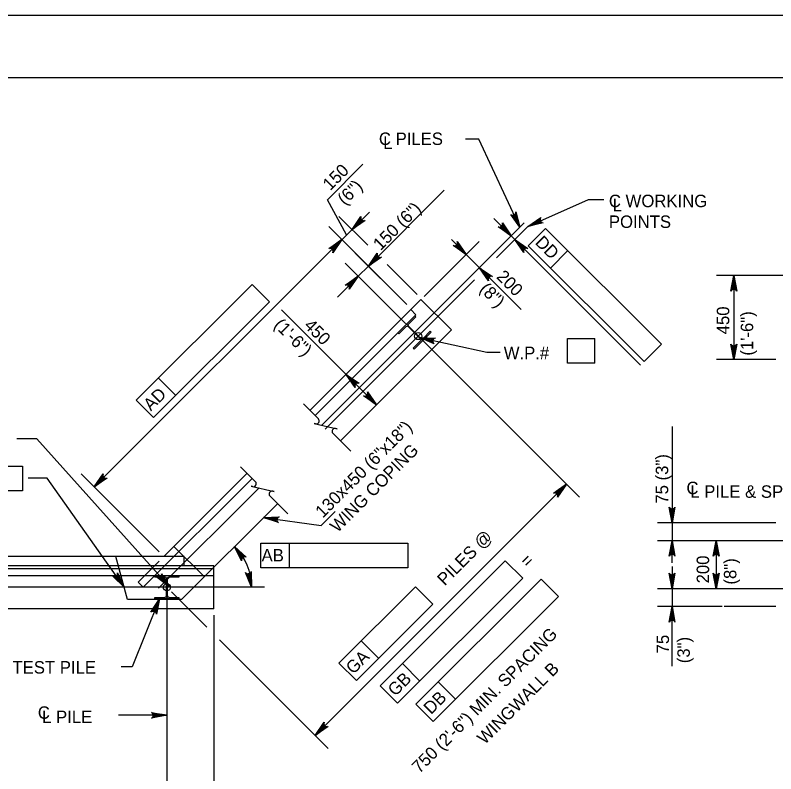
# Model space of a CAD drawing. Extents: x 635440 to 640306, y 296653 to 298484.
# Drawn here: x 639694 to 639876.7, y 298253.1 to 298435.5 of the extents above; entities that cross this region are included whole.
import ezdxf

# ---------------------------------------------------------------- set-up
doc = ezdxf.new("R2010")
doc.units = 0
for name, color, linetype in [('2', 7, 'Continuous'), ('3', 7, 'Continuous'), ('4', 7, 'Continuous'), ('5', 7, 'Continuous'), ('8', 7, 'Continuous'), ('PLT-BNDY', 7, 'Continuous')]:
    doc.layers.add(name, color=color, linetype=linetype)

# ---------------------------------------------------------------- blocks, each defined once
blk = doc.blocks.new('HPILE')
at = {"layer": '3'}
for p, q in [((-0.12, -2.66), (-0.12, 2.66)), ((0.12, 2.66), (0.12, -2.66)), ((-3.67, -3.1), (-0.56, -3.1))]:
    blk.add_line(p, q, dxfattribs=at)
for points in [[(-0.56, 3.1), (-3.67, 3.1), (-3.67, 3.54), (3.67, 3.54), (3.67, 3.1), (0.56, 3.1)], [(0.56, -3.1), (3.67, -3.1), (3.67, -3.54), (-3.67, -3.54), (-3.67, -3.1)]]:
    blk.add_lwpolyline(points, dxfattribs=at)
for centre, start, end in [((-0.56, 2.66), 0, 90), ((0.56, 2.66), 90, 180), ((-0.56, -2.66), 270, 0), ((0.56, -2.66), 180, 270)]:
    blk.add_arc(centre, 0.438, start, end, dxfattribs=at)

msp = doc.modelspace()

# ---------------------------------------------------------------- linework, layer by layer
at = {"layer": '2'}
for p, q in [((639316.46, 298420.46), (640102.46, 298420.46)), ((639764.81, 298340.42), (639791.48, 298367.09)), ((639791.48, 298367.09), (639798.79, 298359.78)), ((639772.11, 298333.11), (639798.79, 298359.78)), ((639729.7, 298305.31), (639749.69, 298325.31)), ((639733.98, 298294.98), (639757, 298318)), ((639732.13, 298307.75), (639739.44, 298300.44)), ((639729.7, 298305.31), (639483.12, 298305.31)), ((639720.95, 298294.98), (639718.19, 298305.31)), ((639741.68, 298292.76), (639741.68, 298302.68)), ((639724.75, 298297.93), (639723.53, 298299.15)), ((639733.98, 298294.98), (639720.95, 298294.98)), ((639741.68, 298292.76), (639472.28, 298292.76))]:
    msp.add_line(p, q, dxfattribs=at)
at = {"layer": '3'}
for p, q in [((639789.04, 298364.66), (639790.26, 298363.44)), ((639766.02, 298339.2), (639790.26, 298363.44)), ((639724.75, 298297.93), (639750.91, 298324.09)), ((639728.55, 298304.16), (639723.53, 298299.15)), ((639734.58, 298305.31), (639729.7, 298305.31)), ((639734.58, 298303.1), (639734.58, 298305.31)), ((639741.68, 298303.1), (639472.28, 298303.1)), ((639472.28, 298302.44), (639741.68, 298302.44)), ((639741.68, 298302.68), (639741.68, 298303.1)), ((639472.28, 298300.71), (639741.68, 298300.71))]:
    msp.add_line(p, q, dxfattribs=at)
at = {"layer": '4'}
for p, q in [((639805.4, 298405.65), (639802.18, 298405.65)), ((639769.02, 298391.1), (639777.53, 298399.6)), ((639778.83, 298375.14), (639797.07, 298393.38)), ((639773.59, 298382.61), (639769.02, 298391.1)), ((639831.75, 298391.11), (639835.37, 298391.11)), ((639778.69, 298380.15), (639771.78, 298387.06)), ((639774.91, 298383.93), (639779.09, 298388.11)), ((639813.16, 298382.4), (639808.99, 298386.58)), ((639788.09, 298365.88), (639769.34, 298384.63)), ((639795.6, 298364.84), (639816.3, 298385.53)), ((639809.59, 298377.09), (639817.16, 298384.67)), ((639770.04, 298379.06), (639774.91, 298383.93)), ((639821.42, 298384.19), (639817.25, 298380.02)), ((639821.42, 298384.19), (639849.27, 298356.35)), ((639712.99, 298322.02), (639772.47, 298381.49)), ((639792.24, 298367.86), (639805.46, 298381.07)), ((639802.32, 298377.94), (639798.78, 298381.49)), ((639813.16, 298382.4), (639814.03, 298381.53)), ((639814.03, 298381.53), (639844.24, 298351.33)), ((639770.39, 298379.41), (639768.3, 298377.32)), ((639817.25, 298380.02), (639845.09, 298352.18)), ((639788.09, 298365.88), (639775.7, 298378.27)), ((639805.51, 298374.75), (639802.33, 298377.94)), ((639826.77, 298378.85), (639822.6, 298374.67)), ((639773.26, 298375.83), (639802.31, 298346.79)), ((639790.53, 298368.32), (639783.33, 298375.51)), ((639778.83, 298375.14), (639776.39, 298372.7)), ((639805.51, 298374.75), (639815.55, 298364.71)), ((639776.39, 298372.7), (639771.39, 298367.7)), ((639796.47, 298363.97), (639804.35, 298371.85)), ((639881.05, 298372.84), (639862.47, 298372.84)), ((639866.62, 298372.84), (639866.62, 298352.66)), ((639723.05, 298342.87), (639750.89, 298370.71)), ((639750.89, 298370.71), (639755.07, 298366.53)), ((639727.23, 298338.69), (639755.07, 298366.53)), ((639773.49, 298349.1), (639757.98, 298364.61)), ((639767.63, 298336.87), (639796.16, 298365.4)), ((639768.43, 298335.93), (639796.96, 298364.47)), ((639826.69, 298351.82), (639826.69, 298357.72)), ((639826.69, 298357.72), (639833.28, 298357.72)), ((639833.28, 298351.82), (639833.28, 298357.72)), ((639849.27, 298356.35), (639845.09, 298352.18)), ((639774.09, 298349.7), (639776.62, 298352.24)), ((639833.28, 298351.82), (639826.69, 298351.82)), ((639876.69, 298352.66), (639862.47, 298352.66)), ((639728.4, 298348.21), (639732.58, 298344.04)), ((639780.8, 298341.8), (639773.49, 298349.1)), ((639802.31, 298346.79), (639829.55, 298319.54)), ((639781.4, 298342.39), (639783.93, 298344.93)), ((639723.05, 298342.87), (639727.23, 298338.69)), ((639851.8, 298336.58), (639851.8, 298313.44)), ((639654.53, 298327.02), (639695.74, 298327.02)), ((639695.74, 298327.02), (639695.74, 298321.11)), ((639728.61, 298306.4), (639709.86, 298325.15)), ((639766.05, 298262.3), (639826.42, 298322.67)), ((639695.74, 298321.11), (639654.53, 298321.11)), ((639728.45, 298297.69), (639752.52, 298321.76)), ((639728.61, 298306.4), (639716.22, 298318.79)), ((639876.69, 298313.44), (639848.28, 298313.44)), ((639851.8, 298313.44), (639851.8, 298309.11)), ((639753.01, 298308.53), (639788.31, 298308.53)), ((639753.01, 298302.62), (639753.01, 298308.53)), ((639759.85, 298302.62), (639759.85, 298308.53)), ((639788.31, 298308.53), (639788.31, 298302.62)), ((639904.09, 298309.11), (639848.28, 298309.11)), ((639851.8, 298303.75), (639851.8, 298309.11)), ((639862.39, 298309.11), (639862.39, 298297.57)), ((639781.67, 298274.2), (639811.74, 298304.27)), ((639811.74, 298304.27), (639815.91, 298300.09)), ((639788.31, 298302.62), (639753.01, 298302.62)), ((639851.8, 298302.92), (639851.8, 298297.57)), ((639785.85, 298270.02), (639815.91, 298300.09)), ((639790.24, 298269.81), (639820.31, 298299.88)), ((639820.31, 298299.88), (639824.49, 298295.7)), ((639753.9, 298297.93), (639458.72, 298297.93)), ((639731.51, 298296.84), (639740.04, 298288.32)), ((639771.78, 298279.69), (639790.12, 298298.03)), ((639790.12, 298298.03), (639794.3, 298293.85)), ((639893.99, 298297.57), (639848.28, 298297.57)), ((639851.8, 298297.57), (639851.8, 298293.25)), ((639730.43, 298296.39), (639730.43, 298236.13)), ((639794.42, 298265.63), (639824.49, 298295.7)), ((639775.96, 298275.51), (639794.3, 298293.85)), ((639863.83, 298293.25), (639848.28, 298293.25)), ((639851.8, 298278.96), (639851.8, 298293.25)), ((639876.69, 298293.25), (639864.34, 298293.25)), ((639741.68, 298291.22), (639741.68, 298221.99)), ((639743.11, 298285.24), (639769.19, 298259.17)), ((639777.13, 298285.03), (639781.3, 298280.86)), ((639722.12, 298278.77), (639719.42, 298278.77)), ((639771.78, 298279.69), (639775.96, 298275.51)), ((639787.02, 298279.55), (639791.19, 298275.37)), ((639795.59, 298275.16), (639799.77, 298270.98)), ((639781.67, 298274.2), (639785.85, 298270.02)), ((639790.24, 298269.81), (639794.42, 298265.63)), ((639730.43, 298267.13), (639718.81, 298267.13))]:
    msp.add_line(p, q, dxfattribs=at)
for points in [[(639815.24, 298384.48), (639805.4, 298405.65)], [(639817.16, 298384.67), (639831.75, 298391.11)], [(639815.24, 298384.48), (639813.04, 298387.57), (639813.34, 298387.39), (639813.63, 298387.36), (639813.87, 298387.43), (639814.08, 298387.57), (639814.24, 298387.81), (639814.3, 298388.16), (639815.24, 298384.48), (639814.24, 298387.81), (639814.08, 298387.57), (639815.24, 298384.48), (639813.87, 298387.43), (639813.63, 298387.36), (639815.24, 298384.48), (639813.34, 298387.39)], [(639774.91, 298383.93), (639777.05, 298387.06), (639776.99, 298386.72), (639777.06, 298386.43), (639777.21, 298386.23), (639777.41, 298386.08), (639777.7, 298386.01), (639778.04, 298386.07), (639774.91, 298383.93), (639777.7, 298386.01), (639777.41, 298386.08), (639774.91, 298383.93), (639777.21, 298386.23), (639777.06, 298386.43), (639774.91, 298383.93), (639776.99, 298386.72)], [(639817.16, 298384.67), (639820.29, 298386.81), (639820.11, 298386.51), (639820.07, 298386.23), (639820.14, 298385.98), (639820.28, 298385.77), (639820.51, 298385.6), (639820.86, 298385.53), (639817.16, 298384.67), (639820.51, 298385.6), (639820.28, 298385.77), (639817.16, 298384.67), (639820.14, 298385.98), (639820.07, 298386.23), (639817.16, 298384.67), (639820.11, 298386.51)], [(639813.16, 298382.4), (639810.03, 298384.55), (639810.38, 298384.48), (639810.66, 298384.56), (639810.87, 298384.7), (639811.01, 298384.91), (639811.08, 298385.19), (639811.02, 298385.53), (639813.16, 298382.4), (639811.08, 298385.19), (639811.01, 298384.91), (639813.16, 298382.4), (639810.87, 298384.7), (639810.66, 298384.56), (639813.16, 298382.4), (639810.38, 298384.48)], [(639772.47, 298381.49), (639770.33, 298378.36), (639770.39, 298378.71), (639770.32, 298378.99), (639770.17, 298379.2), (639769.97, 298379.34), (639769.69, 298379.42), (639769.34, 298379.35), (639772.47, 298381.49), (639769.69, 298379.42), (639769.97, 298379.34), (639772.47, 298381.49), (639770.17, 298379.2), (639770.32, 298378.99), (639772.47, 298381.49), (639770.39, 298378.71)], [(639802.32, 298377.94), (639799.19, 298380.08), (639799.54, 298380.02), (639799.82, 298380.09), (639800.03, 298380.24), (639800.17, 298380.44), (639800.24, 298380.73), (639800.18, 298381.07), (639802.32, 298377.94), (639800.24, 298380.73), (639800.17, 298380.44), (639802.32, 298377.94), (639800.03, 298380.24), (639799.82, 298380.09), (639802.32, 298377.94), (639799.54, 298380.02)], [(639814.03, 298381.53), (639817.16, 298379.39), (639816.82, 298379.46), (639816.54, 298379.38), (639816.33, 298379.24), (639816.19, 298379.03), (639816.11, 298378.75), (639816.17, 298378.4), (639814.03, 298381.53), (639816.11, 298378.75), (639816.19, 298379.03), (639814.03, 298381.53), (639816.33, 298379.24), (639816.54, 298379.38), (639814.03, 298381.53), (639816.82, 298379.46)], [(639778.83, 298375.14), (639780.97, 298378.27), (639780.91, 298377.93), (639780.98, 298377.64), (639781.13, 298377.44), (639781.34, 298377.29), (639781.62, 298377.22), (639781.96, 298377.28), (639778.83, 298375.14), (639781.62, 298377.22), (639781.34, 298377.29), (639778.83, 298375.14), (639781.13, 298377.44), (639780.98, 298377.64), (639778.83, 298375.14), (639780.91, 298377.93)], [(639805.51, 298374.75), (639808.65, 298372.61), (639808.3, 298372.67), (639808.02, 298372.6), (639807.81, 298372.45), (639807.67, 298372.25), (639807.59, 298371.97), (639807.66, 298371.62), (639805.51, 298374.75), (639807.59, 298371.97), (639807.67, 298372.25), (639805.51, 298374.75), (639807.81, 298372.45), (639808.02, 298372.6), (639805.51, 298374.75), (639808.3, 298372.67)], [(639776.39, 298372.7), (639774.25, 298369.57), (639774.31, 298369.91), (639774.24, 298370.2), (639774.1, 298370.4), (639773.89, 298370.55), (639773.61, 298370.62), (639773.26, 298370.56), (639776.39, 298372.7), (639773.61, 298370.62), (639773.89, 298370.55), (639776.39, 298372.7), (639774.1, 298370.4), (639774.24, 298370.2), (639776.39, 298372.7), (639774.31, 298369.91)], [(639866.62, 298372.84), (639867.32, 298369.12), (639867.12, 298369.4), (639866.87, 298369.55), (639866.62, 298369.59), (639866.37, 298369.55), (639866.12, 298369.4), (639865.92, 298369.12), (639866.62, 298372.84), (639866.12, 298369.4), (639866.37, 298369.55), (639866.62, 298372.84), (639866.62, 298369.59), (639866.87, 298369.55), (639866.62, 298372.84), (639867.12, 298369.4)], [(639791.15, 298357.95), (639807.27, 298354.4), (639810.49, 298354.4)], [(639791.15, 298357.95), (639794.94, 298357.83), (639794.62, 298357.69), (639794.42, 298357.48), (639794.32, 298357.25), (639794.31, 298356.99), (639794.4, 298356.72), (639794.64, 298356.46), (639791.15, 298357.95), (639794.4, 298356.72), (639794.31, 298356.99), (639791.15, 298357.95), (639794.32, 298357.25), (639794.42, 298357.48), (639791.15, 298357.95), (639794.62, 298357.69)], [(639866.62, 298352.66), (639865.92, 298356.39), (639866.12, 298356.1), (639866.37, 298355.95), (639866.62, 298355.91), (639866.87, 298355.95), (639867.12, 298356.1), (639867.32, 298356.39), (639866.62, 298352.66), (639867.12, 298356.1), (639866.87, 298355.95), (639866.62, 298352.66), (639866.62, 298355.91), (639866.37, 298355.95), (639866.62, 298352.66), (639866.12, 298356.1)], [(639773.49, 298349.1), (639776.62, 298346.96), (639776.27, 298347.02), (639775.99, 298346.95), (639775.79, 298346.81), (639775.64, 298346.6), (639775.57, 298346.32), (639775.63, 298345.97), (639773.49, 298349.1), (639775.57, 298346.32), (639775.64, 298346.6), (639773.49, 298349.1), (639775.79, 298346.81), (639775.99, 298346.95), (639773.49, 298349.1), (639776.27, 298347.02)], [(639780.8, 298341.8), (639777.66, 298343.94), (639778.01, 298343.87), (639778.29, 298343.95), (639778.5, 298344.09), (639778.64, 298344.3), (639778.72, 298344.58), (639778.65, 298344.93), (639780.8, 298341.8), (639778.72, 298344.58), (639778.64, 298344.3), (639780.8, 298341.8), (639778.5, 298344.09), (639778.29, 298343.95), (639780.8, 298341.8), (639778.01, 298343.87)], [(639731.13, 298297.93), (639699.16, 298333.61), (639694.39, 298333.61)], [(639712.99, 298322.02), (639715.13, 298325.15), (639715.07, 298324.8), (639715.15, 298324.52), (639715.29, 298324.31), (639715.5, 298324.17), (639715.78, 298324.09), (639716.12, 298324.16), (639712.99, 298322.02), (639715.78, 298324.09), (639715.5, 298324.17), (639712.99, 298322.02), (639715.29, 298324.31), (639715.15, 298324.52), (639712.99, 298322.02), (639715.07, 298324.8)], [(639720.16, 298297.93), (639701.71, 298324.18), (639697.1, 298324.18)], [(639826.42, 298322.67), (639824.28, 298319.54), (639824.34, 298319.89), (639824.27, 298320.17), (639824.12, 298320.38), (639823.92, 298320.52), (639823.63, 298320.59), (639823.29, 298320.53), (639826.42, 298322.67), (639823.63, 298320.59), (639823.92, 298320.52), (639826.42, 298322.67), (639824.12, 298320.38), (639824.27, 298320.17), (639826.42, 298322.67), (639824.34, 298319.89)], [(639851.8, 298313.44), (639851.1, 298317.17), (639851.3, 298316.88), (639851.55, 298316.73), (639851.8, 298316.69), (639852.05, 298316.73), (639852.3, 298316.88), (639852.5, 298317.17), (639851.8, 298313.44), (639852.3, 298316.88), (639852.05, 298316.73), (639851.8, 298313.44), (639851.8, 298316.69), (639851.55, 298316.73), (639851.8, 298313.44), (639851.3, 298316.88)], [(639753.65, 298314.65), (639767.53, 298312.73), (639770.89, 298316.09)], [(639753.65, 298314.65), (639757.44, 298314.83), (639757.12, 298314.68), (639756.94, 298314.45), (639756.87, 298314.2), (639756.88, 298313.95), (639756.99, 298313.68), (639757.24, 298313.45), (639753.65, 298314.65), (639756.99, 298313.68), (639756.88, 298313.95), (639753.65, 298314.65), (639756.87, 298314.2), (639756.94, 298314.45), (639753.65, 298314.65), (639757.12, 298314.68)], [(639851.8, 298309.11), (639852.5, 298305.38), (639852.3, 298305.67), (639852.05, 298305.82), (639851.8, 298305.86), (639851.55, 298305.82), (639851.3, 298305.67), (639851.1, 298305.38), (639851.8, 298309.11), (639851.3, 298305.67), (639851.55, 298305.82), (639851.8, 298309.11), (639851.8, 298305.86), (639852.05, 298305.82), (639851.8, 298309.11), (639852.3, 298305.67)], [(639862.39, 298309.11), (639863.09, 298305.38), (639862.89, 298305.67), (639862.64, 298305.82), (639862.39, 298305.86), (639862.14, 298305.82), (639861.89, 298305.67), (639861.69, 298305.38), (639862.39, 298309.11), (639861.89, 298305.67), (639862.14, 298305.82), (639862.39, 298309.11), (639862.39, 298305.86), (639862.64, 298305.82), (639862.39, 298309.11), (639862.89, 298305.67)], [(639746.71, 298307.71), (639749.5, 298305.14), (639749.17, 298305.25), (639748.88, 298305.22), (639748.66, 298305.1), (639748.48, 298304.92), (639748.37, 298304.65), (639748.38, 298304.3), (639746.71, 298307.71), (639748.37, 298304.65), (639748.48, 298304.92), (639746.71, 298307.71), (639748.66, 298305.1), (639748.88, 298305.22), (639746.71, 298307.71), (639749.17, 298305.25)], [(639720.16, 298297.93), (639717.44, 298300.58), (639717.77, 298300.46), (639718.06, 298300.48), (639718.29, 298300.59), (639718.47, 298300.77), (639718.59, 298301.03), (639718.59, 298301.38), (639720.16, 298297.93), (639718.59, 298301.03), (639718.47, 298300.77), (639720.16, 298297.93), (639718.29, 298300.59), (639718.06, 298300.48), (639720.16, 298297.93), (639717.77, 298300.46)], [(639731.13, 298297.93), (639728.12, 298300.24), (639728.46, 298300.16), (639728.75, 298300.21), (639728.96, 298300.35), (639729.12, 298300.55), (639729.21, 298300.82), (639729.16, 298301.17), (639731.13, 298297.93), (639729.21, 298300.82), (639729.12, 298300.55), (639731.13, 298297.93), (639728.96, 298300.35), (639728.75, 298300.21), (639731.13, 298297.93), (639728.46, 298300.16)], [(639750.76, 298297.93), (639749.34, 298301.45), (639749.59, 298301.21), (639749.87, 298301.11), (639750.12, 298301.12), (639750.36, 298301.21), (639750.58, 298301.4), (639750.72, 298301.72), (639750.76, 298297.93), (639750.58, 298301.4), (639750.36, 298301.21), (639750.76, 298297.93), (639750.12, 298301.12), (639749.87, 298301.11), (639750.76, 298297.93), (639749.59, 298301.21)], [(639851.8, 298297.57), (639851.1, 298301.3), (639851.3, 298301.02), (639851.55, 298300.87), (639851.8, 298300.82), (639852.05, 298300.87), (639852.3, 298301.02), (639852.5, 298301.3), (639851.8, 298297.57), (639852.3, 298301.02), (639852.05, 298300.87), (639851.8, 298297.57), (639851.8, 298300.82), (639851.55, 298300.87), (639851.8, 298297.57), (639851.3, 298301.02)], [(639862.39, 298297.57), (639861.69, 298301.3), (639861.89, 298301.02), (639862.14, 298300.87), (639862.39, 298300.82), (639862.64, 298300.87), (639862.89, 298301.02), (639863.09, 298301.3), (639862.39, 298297.57), (639862.89, 298301.02), (639862.64, 298300.87), (639862.39, 298297.57), (639862.39, 298300.82), (639862.14, 298300.87), (639862.39, 298297.57), (639861.89, 298301.02)], [(639728.63, 298295.15), (639722.12, 298278.77)], [(639728.63, 298295.15), (639727.9, 298291.42), (639727.82, 298291.76), (639727.65, 298291.99), (639727.43, 298292.13), (639727.18, 298292.18), (639726.9, 298292.13), (639726.61, 298291.94), (639728.63, 298295.15), (639726.9, 298292.13), (639727.18, 298292.18), (639728.63, 298295.15), (639727.43, 298292.13), (639727.65, 298291.99), (639728.63, 298295.15), (639727.82, 298291.76)], [(639851.8, 298293.25), (639852.5, 298289.52), (639852.3, 298289.81), (639852.05, 298289.96), (639851.8, 298290), (639851.55, 298289.96), (639851.3, 298289.81), (639851.1, 298289.52), (639851.8, 298293.25), (639851.3, 298289.81), (639851.55, 298289.96), (639851.8, 298293.25), (639851.8, 298290), (639852.05, 298289.96), (639851.8, 298293.25), (639852.3, 298289.81)], [(639730.43, 298267.13), (639726.7, 298266.43), (639726.99, 298266.63), (639727.13, 298266.88), (639727.18, 298267.13), (639727.13, 298267.38), (639726.99, 298267.63), (639726.7, 298267.83), (639730.43, 298267.13), (639726.99, 298267.63), (639727.13, 298267.38), (639730.43, 298267.13), (639727.18, 298267.13), (639727.13, 298266.88), (639730.43, 298267.13), (639726.99, 298266.63)], [(639766.05, 298262.3), (639768.19, 298265.44), (639768.13, 298265.09), (639768.2, 298264.81), (639768.35, 298264.6), (639768.56, 298264.46), (639768.84, 298264.38), (639769.18, 298264.45), (639766.05, 298262.3), (639768.84, 298264.38), (639768.56, 298264.46), (639766.05, 298262.3), (639768.35, 298264.6), (639768.2, 298264.81), (639766.05, 298262.3), (639768.13, 298265.09)]]:
    msp.add_lwpolyline(points, dxfattribs=at)
for points in [[(639776.65, 298386.37), (639777.35, 298385.67), (639774.91, 298383.93)], [(639815.24, 298384.48), (639814.22, 298387.26), (639813.77, 298387.06)], [(639811.42, 298384.84), (639810.73, 298384.14), (639813.16, 298382.4)], [(639817.16, 298384.67), (639819.96, 298385.63), (639819.77, 298386.08)], [(639770.04, 298379.76), (639770.73, 298379.06), (639772.47, 298381.49)], [(639816.47, 298379.79), (639815.77, 298379.1), (639814.03, 298381.53)], [(639800.58, 298380.38), (639799.89, 298379.68), (639802.33, 298377.94)], [(639780.57, 298377.57), (639781.27, 298376.88), (639778.83, 298375.14)], [(639807.95, 298373.01), (639807.25, 298372.32), (639805.51, 298374.75)], [(639773.96, 298370.96), (639774.65, 298370.27), (639776.39, 298372.7)], [(639866.16, 298370.08), (639867.08, 298370.08), (639866.62, 298372.84)], [(639791.15, 298357.95), (639793.98, 298357.07), (639794.09, 298357.55)], [(639866.16, 298355.43), (639867.08, 298355.43), (639866.62, 298352.66)], [(639775.92, 298347.36), (639775.23, 298346.67), (639773.49, 298349.1)], [(639779.06, 298344.23), (639778.36, 298343.53), (639780.8, 298341.8)], [(639714.73, 298324.45), (639715.43, 298323.75), (639712.99, 298322.02)], [(639823.99, 298320.93), (639824.68, 298320.24), (639826.42, 298322.67)], [(639852.28, 298316.32), (639851.32, 298316.32), (639851.8, 298313.44)], [(639753.65, 298314.65), (639756.54, 298314), (639756.61, 298314.49)], [(639852.28, 298306.23), (639851.32, 298306.23), (639851.8, 298309.11)], [(639862.87, 298306.23), (639861.91, 298306.23), (639862.39, 298309.11)], [(639720.16, 298297.93), (639718.66, 298300.49), (639718.26, 298300.2)], [(639852.28, 298300.46), (639851.32, 298300.46), (639851.8, 298297.57)], [(639862.87, 298300.46), (639861.91, 298300.46), (639862.39, 298297.57)], [(639731.13, 298297.93), (639729.34, 298300.29), (639728.98, 298299.96)], [(639728.63, 298295.15), (639727.31, 298292.49), (639727.77, 298292.31)], [(639852.28, 298290.37), (639851.32, 298290.37), (639851.8, 298293.25)], [(639727.47, 298266.64), (639727.47, 298267.62), (639730.43, 298267.13)], [(639767.79, 298264.74), (639768.49, 298264.04), (639766.05, 298262.3)]]:
    msp.add_lwpolyline(points, close=True, dxfattribs=at)
for centre in [(639790.8, 298358.3), (639730.43, 298297.93)]:
    msp.add_circle(centre, 0.85, dxfattribs=at)
msp.add_arc((639736.93, 298297.93), 13.83, 359.9984, 45.0026, dxfattribs=at)
at = {"layer": '8'}
for p, q in [((639763.25, 298341.98), (639766.83, 298338.39)), ((639770.27, 298334.96), (639774.59, 298330.64)), ((639748.13, 298326.88), (639751.72, 298323.29)), ((639755.15, 298319.86), (639759.47, 298315.54))]:
    msp.add_line(p, q, dxfattribs=at)
for points in [[(639766.15, 298337.2), (639765.81, 298337.28), (639771.35, 298336.02), (639770.97, 298336.1)], [(639751.03, 298322.1), (639750.68, 298322.18), (639756.23, 298320.92), (639755.85, 298321)]]:
    msp.add_lwpolyline(points, dxfattribs=at)
for centre, start, end in [((639766.33, 298337.89), 255, 45), ((639770.82, 298335.41), 77.1328, 219.6714), ((639751.21, 298322.79), 255, 45), ((639755.7, 298320.31), 77.1328, 219.6714)]:
    msp.add_arc(centre, 0.71, start, end, dxfattribs=at)
at = {"layer": 'PLT-BNDY'}
msp.add_lwpolyline([(639276.46, 298435.46), (640117.46, 298435.46), (640117.46, 297841.46), (639276.46, 297841.46)], close=True, dxfattribs=at)

# ---------------------------------------------------------------- block references
at = {"layer": '3', "xscale": 0.78743606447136, "yscale": -0.7874360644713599, "rotation": -134.9999999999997}
msp.add_blockref('HPILE', (639789.93, 298359.17), dxfattribs=at)
at = {"layer": '3', "xscale": 0.78743606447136, "yscale": 0.78743606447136}
msp.add_blockref('HPILE', (639730.43, 298297.93), dxfattribs=at)

# ---------------------------------------------------------------- texts
at = {"layer": '4'}
for s, height, p in [('C PILES', 3, (639781.37, 298404.25)), ('L', 3, (639782.4, 298403.31)), ('C WORKING', 3, (639836.62, 298389.3)), ('L', 3, (639837.52, 298388.31)), ('POINTS', 3, (639836.62, 298384.3)), ('W.P.#', 3, (639811.36, 298352.75)), ('C', 3, (639855.25, 298320.29)), ('L PILE & SPLICE', 3.0001, (639856.18, 298319.42)), ('AB', 3, (639753.18, 298304.11)), ('TEST PILE', 3, (639693.34, 298277.16)), ('C', 3, (639699.43, 298266.28)), ('L PILE', 3, (639700.46, 298265.24))]:
    msp.add_text(s, height=height, dxfattribs=at).set_placement(p)
for s, height, rotation, p in [('DD', 3, 315, (639818.71, 298380.61)), ('200', 3, 315, (639809.41, 298372.38)), ('(8")', 3, 315, (639805.35, 298369.37)), ('AD', 3, 45, (639726.6, 298340.12)), ('PILES @', 3, 44.9382, (639797.17, 298298.1)), ('=', 3, 44.9382, (639817.13, 298302.45)), ('750 (2\'-6") MIN. SPACING', 3.0001, 45, (639791.09, 298253.02)), ('GA', 3, 44.9382, (639775.23, 298276.84)), ('WINGWALL B', 3, 45, (639806.76, 298259.95)), ('GB', 3, 44.9382, (639785.3, 298271.54)), ('DB', 3, 44.9382, (639793.91, 298267.18))]:
    msp.add_text(s, height=height, rotation=rotation, dxfattribs=at).set_placement(p)
at = {"layer": '5'}
for s, height, rotation, p in [('150', 3, 45, (639769.67, 298393.12)), ('(6")', 3, 45, (639773.21, 298389.59)), ('150 (6")', 3, 45, (639781.76, 298378.71)), ('450', 3, 90, (639865.54, 298358.73)), ('(1\'-6")', 3, 90, (639871.28, 298353.61)), ('(1\'-6")', 3, 315, (639755.96, 298360.76)), ('450', 3, 315, (639763.18, 298360.62)), ('130x450 (6"x18")', 3.0001, 45, (639767.89, 298314.41)), ('WING COPING', 3.0001, 45, (639771.43, 298310.88)), ('75 (3")', 3, 90, (639850.87, 298318.02)), ('200', 3, 90, (639860.7, 298298.84)), ('(8")', 3, 90, (639867.24, 298298.56)), ('75', 3, 90, (639851.06, 298282.02)), ('(3")', 3, 90, (639856.06, 298279.65))]:
    msp.add_text(s, height=height, rotation=rotation, dxfattribs=at).set_placement(p)

doc.saveas('drawing.dxf')
